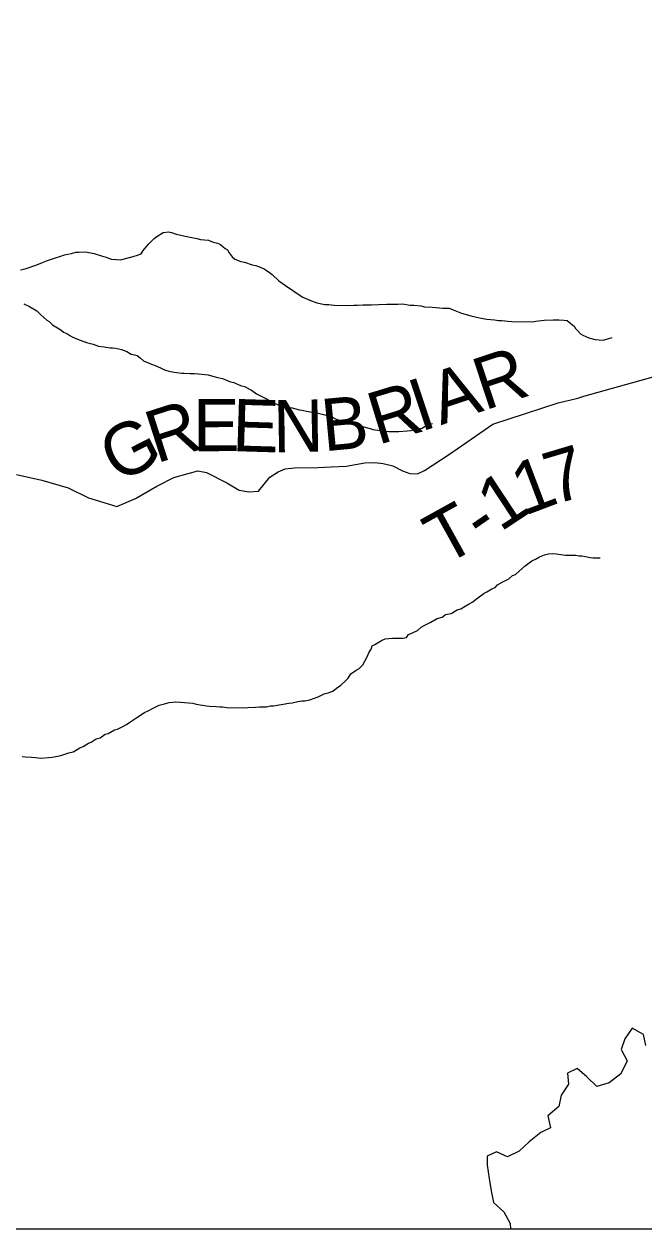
# Model space of a CAD drawing. Extents: x 0 to 34, y 0 to 22.
# Drawn here: x 6.804 to 7.478, y 14.1 to 15.409 of the extents above; entities that cross this region are included whole.
import ezdxf

# ---------------------------------------------------------------- set-up
doc = ezdxf.new("R2010")
doc.units = 0
for name, color, linetype in [('GM_X_Corporation', 7, 'Continuous'), ('GM_X_Major_Lake', 7, 'Continuous'), ('GM_X_Minor_River', 7, 'Continuous'), ('GM_X_Township_Road', 7, 'Continuous'), ('GM_X_Township_Road_Text', 7, 'Continuous'), ('SH_Data', 7, 'Continuous')]:
    doc.layers.add(name, color=color, linetype=linetype)

msp = doc.modelspace()

# ---------------------------------------------------------------- linework, layer by layer
at = {"layer": 'GM_X_Corporation'}
msp.add_lwpolyline([(2.9271, 14.1), (8.843, 14.1), (8.8335, 14.8989), (8.9, 15.0205), (8.9, 18.9286)], dxfattribs=at)
at = {"layer": 'GM_X_Major_Lake'}
msp.add_lwpolyline([(7.4799, 14.2992), (7.4774, 14.3114), (7.465, 14.3181), (7.4572, 14.3064), (7.4532, 14.2951), (7.4595, 14.2828), (7.4528, 14.2685), (7.4401, 14.2588), (7.4267, 14.2548), (7.4159, 14.2653), (7.4054, 14.2742), (7.3947, 14.2694), (7.396, 14.2572), (7.3878, 14.2452), (7.3853, 14.2331), (7.3734, 14.223), (7.3762, 14.21), (7.3659, 14.2049), (7.3532, 14.1948), (7.3424, 14.1844), (7.3294, 14.1785), (7.3177, 14.1836), (7.3073, 14.1789), (7.3076, 14.1694), (7.3096, 14.1549), (7.3117, 14.1412), (7.3145, 14.1286), (7.3257, 14.1185), (7.3324, 14.1058), (7.3328, 14.1)], dxfattribs=at)
at = {"layer": 'GM_X_Minor_River'}
for points in [[(6.8178, 15.1476), (6.8239, 15.1501), (6.8293, 15.1523), (6.8327, 15.1534), (6.8392, 15.1556), (6.8419, 15.1563), (6.848, 15.1585), (6.8514, 15.1592), (6.8556, 15.1598), (6.8602, 15.1613), (6.8636, 15.1616), (6.8709, 15.1619), (6.8803, 15.1598), (6.8894, 15.157), (6.8921, 15.1562), (6.8958, 15.155), (6.8992, 15.1538), (6.9046, 15.1533), (6.9087, 15.1532), (6.9187, 15.1557), (6.9225, 15.1568), (6.9274, 15.1582), (6.9313, 15.1597), (6.9336, 15.1634), (6.9398, 15.1705), (6.9456, 15.1761), (6.9483, 15.1784), (6.9552, 15.1828), (6.9613, 15.1835), (6.9644, 15.1827), (6.9693, 15.1811), (6.981, 15.1786), (6.992, 15.1761), (6.9958, 15.1753), (7.0045, 15.1744), (7.0094, 15.1724), (7.0143, 15.1711), (7.0177, 15.1696), (7.0226, 15.1653), (7.0253, 15.1641), (7.0271, 15.1606), (7.0304, 15.1564), (7.0331, 15.1537), (7.0395, 15.1513), (7.0437, 15.1505), (7.052, 15.1477), (7.0561, 15.1468), (7.0626, 15.1444), (7.0652, 15.1433), (7.0708, 15.1394), (7.0738, 15.137), (7.0809, 15.1301), (7.0847, 15.1277), (7.0918, 15.1226), (7.0949, 15.1207), (7.0997, 15.1172), (7.1069, 15.1125), (7.1095, 15.1113), (7.1148, 15.1093), (7.1224, 15.1065), (7.1311, 15.1045), (7.1353, 15.1044), (7.1413, 15.1039), (7.1562, 15.1036), (7.1626, 15.1039), (7.1664, 15.1038), (7.1725, 15.1041), (7.1813, 15.1043), (7.1893, 15.1046), (7.198, 15.1048), (7.2105, 15.105), (7.2155, 15.1053), (7.2238, 15.104), (7.2276, 15.1039), (7.2352, 15.103), (7.2394, 15.1022), (7.2478, 15.1017), (7.2519, 15.1012), (7.2591, 15.1007), (7.266, 15.1006), (7.2705, 15.0986), (7.2758, 15.0966), (7.2796, 15.095), (7.2834, 15.0942), (7.2898, 15.0922), (7.2943, 15.091), (7.3008, 15.0897), (7.3072, 15.0888), (7.3156, 15.0879), (7.3197, 15.0871), (7.3235, 15.087), (7.33, 15.0865), (7.3342, 15.0861), (7.3566, 15.0857), (7.3604, 15.0864), (7.3695, 15.0874), (7.3791, 15.088), (7.3859, 15.0878), (7.3908, 15.0874), (7.3946, 15.0873), (7.3984, 15.0838)], [(6.8002, 15.1422), (6.8052, 15.1432), (6.8178, 15.1476)], [(6.8038, 15.1052), (6.8098, 15.1025), (6.8177, 15.0978), (6.8222, 15.0935), (6.8286, 15.0877), (6.8312, 15.0861), (6.8349, 15.0826), (6.844, 15.0772), (6.847, 15.0744), (6.8504, 15.0729), (6.8537, 15.0709), (6.8564, 15.0693), (6.862, 15.0669), (6.8651, 15.0658), (6.8719, 15.0634), (6.8791, 15.0613), (6.8851, 15.0593), (6.8912, 15.0585), (6.8976, 15.0576), (6.9003, 15.0575), (6.9033, 15.0571), (6.9101, 15.0558), (6.9158, 15.0535), (6.9203, 15.0507), (6.9241, 15.0499), (6.9271, 15.0491), (6.9301, 15.0467), (6.9339, 15.0433), (6.9426, 15.0397), (6.9467, 15.0381), (6.9524, 15.0357), (6.9565, 15.0337), (6.9614, 15.0321), (6.9671, 15.0309), (6.9755, 15.03), (6.9781, 15.0299), (6.9846, 15.0294), (6.9892, 15.0297), (6.9937, 15.0293), (7.0043, 15.0283), (7.0127, 15.0255), (7.0199, 15.0243), (7.0285, 15.0207), (7.032, 15.0199), (7.0376, 15.0171), (7.0403, 15.0163), (7.0437, 15.0155), (7.0512, 15.0116), (7.0568, 15.0076), (7.0617, 15.0049), (7.0689, 15.0014), (7.0734, 14.9979), (7.0776, 14.9966), (7.0844, 14.9942), (7.0885, 14.993), (7.0954, 14.9921), (7.1033, 14.9901), (7.106, 14.9897), (7.1128, 14.9884), (7.1154, 14.988), (7.12, 14.9872), (7.1238, 14.9863), (7.131, 14.9847), (7.1374, 14.9827), (7.1434, 14.9799), (7.1506, 14.9775), (7.1533, 14.9763), (7.1586, 14.9751), (7.165, 14.9734), (7.1703, 14.9722), (7.1801, 14.9697), (7.1832, 14.9686), (7.1911, 14.9677), (7.1949, 14.9672), (7.2002, 14.9667), (7.2113, 14.9665), (7.2204, 14.9671), (7.2246, 14.9675), (7.2307, 14.9692), (7.2368, 14.9703), (7.2426, 14.974), (7.2452, 14.9747), (7.2479, 14.9754)], [(7.3984, 15.0838), (7.4021, 15.0811), (7.4036, 15.0784), (7.4062, 15.0761), (7.4088, 15.0726), (7.4115, 15.0714), (7.4179, 15.0683), (7.4247, 15.0666), (7.4334, 15.0657), (7.4434, 15.0686)], [(7.2358, 14.7539), (7.2389, 14.7558), (7.2462, 14.7594), (7.2531, 14.7635), (7.2584, 14.7649), (7.2623, 14.7675), (7.2684, 14.7689), (7.2749, 14.7726), (7.2787, 14.7737), (7.2837, 14.7767), (7.288, 14.7792), (7.2918, 14.7815), (7.296, 14.7848), (7.3041, 14.7907), (7.3072, 14.7922), (7.3126, 14.7955), (7.316, 14.797), (7.3187, 14.8), (7.3245, 14.8033), (7.331, 14.8066), (7.3349, 14.81), (7.3383, 14.8111), (7.3425, 14.8152), (7.3487, 14.8204), (7.356, 14.826), (7.3599, 14.8278), (7.3645, 14.8304), (7.3698, 14.8326), (7.374, 14.8336), (7.3786, 14.8339), (7.3824, 14.8335), (7.3926, 14.8322), (7.3964, 14.8321), (7.404, 14.832), (7.4071, 14.8315), (7.4105, 14.8315), (7.4143, 14.8307), (7.4196, 14.8298), (7.4226, 14.8294), (7.4302, 14.8292)], [(6.8019, 14.6135), (6.8054, 14.6131), (6.8122, 14.6126), (6.8164, 14.6122), (6.8224, 14.6117), (6.8304, 14.6123), (6.8346, 14.6126), (6.8384, 14.6133), (6.8438, 14.6143), (6.8526, 14.6172), (6.8575, 14.6183), (6.8618, 14.6209), (6.8648, 14.6227), (6.8683, 14.6242), (6.874, 14.6279), (6.8771, 14.629), (6.8825, 14.6327), (6.8867, 14.6337), (6.8921, 14.6375), (6.8955, 14.6385), (6.9024, 14.6422), (6.9055, 14.6429), (6.9108, 14.6455), (6.9154, 14.6481), (6.9201, 14.6514), (6.9266, 14.6559), (6.9351, 14.661), (6.9397, 14.6632), (6.9435, 14.6655), (6.9466, 14.6669), (6.9508, 14.6691), (6.9565, 14.6706), (6.9619, 14.672), (6.9657, 14.6723), (6.9691, 14.6726), (6.974, 14.6725), (6.9828, 14.6716), (6.9873, 14.6712), (6.9911, 14.6703), (7.0025, 14.6686), (7.0055, 14.6682), (7.0127, 14.6677), (7.0169, 14.6672), (7.0199, 14.6672), (7.0245, 14.6667), (7.0283, 14.6663), (7.0332, 14.6666), (7.0427, 14.6664), (7.0473, 14.6667), (7.0557, 14.6669), (7.0599, 14.6672), (7.0629, 14.6672), (7.0675, 14.6675), (7.072, 14.6685), (7.0751, 14.6685), (7.0812, 14.6695), (7.0858, 14.6702), (7.0919, 14.6712), (7.0953, 14.6716), (7.1018, 14.673), (7.106, 14.6737), (7.1094, 14.674), (7.1147, 14.675), (7.1239, 14.6783), (7.1304, 14.6816), (7.1346, 14.6827), (7.1396, 14.6845), (7.1435, 14.6878), (7.1485, 14.6908), (7.1535, 14.6956), (7.1562, 14.6986), (7.1593, 14.7031), (7.1651, 14.7072), (7.1681, 14.7087), (7.1724, 14.7128), (7.1767, 14.7211), (7.1791, 14.7268), (7.1814, 14.7301), (7.1823, 14.7335), (7.1853, 14.735), (7.1926, 14.7395), (7.1964, 14.7413), (7.2003, 14.7416), (7.2044, 14.7419), (7.2113, 14.7418), (7.2162, 14.7421), (7.2197, 14.7428), (7.222, 14.7458), (7.2262, 14.7476), (7.2316, 14.7502), (7.2358, 14.7539)]]:
    msp.add_lwpolyline(points, dxfattribs=at)
at = {"layer": 'GM_X_Township_Road'}
for points in [[(7.4124, 15.0048), (7.5436, 15.0417), (7.5533, 15.0445), (7.5615, 15.05), (7.7278, 15.156), (7.7386, 15.1623), (7.7463, 15.1686), (7.7654, 15.1857), (8.1779, 15.57), (8.2055, 15.5951), (8.2191, 15.6084), (8.2391, 15.6325), (8.2489, 15.6435), (8.2583, 15.655), (8.2679, 15.6699), (8.2752, 15.6869)], [(6.7957, 14.9198), (6.8233, 14.9136), (6.8519, 14.9053), (6.8742, 14.8945), (6.8906, 14.8893), (6.9048, 14.8849), (6.9253, 14.8938), (6.9485, 14.907), (6.967, 14.9164), (6.9825, 14.921), (6.993, 14.9239), (7.0024, 14.922), (7.0243, 14.9106), (7.038, 14.9029), (7.0484, 14.9008), (7.0589, 14.9018), (7.0713, 14.9169), (7.0803, 14.9228), (7.088, 14.9259), (7.0979, 14.9271), (7.1233, 14.9276), (7.1378, 14.9282), (7.1541, 14.9288), (7.1746, 14.9325), (7.1855, 14.9328), (7.1943, 14.9319), (7.2049, 14.9291), (7.2154, 14.9237), (7.2234, 14.9208), (7.2319, 14.9205), (7.2394, 14.9243), (7.2653, 14.9413), (7.3138, 14.9744), (7.3845, 14.9978), (7.4059, 15.0029), (7.4124, 15.0048)]]:
    msp.add_lwpolyline(points, dxfattribs=at)
at = {"layer": 'SH_Data'}
msp.add_line((2.1, 14.1), (8.9, 14.1), dxfattribs=at)

# ---------------------------------------------------------------- texts
at = {"layer": 'GM_X_Township_Road_Text'}
for s, rotation, p in [('R', 18.3634, (7.3044, 14.9892)), ('A', 18.5657, (7.2571, 14.9733)), ('R', 16.994, (7.1887, 14.9517)), ('I', 18.4655, (7.2348, 14.9659)), ('B', 5.3907, (7.1299, 14.9449)), ('R', 17.8055, (6.9478, 14.9316)), ('E', 0.15, (6.9877, 14.9451)), ('E', 358.2341, (7.0297, 14.9453)), ('N', 0.8092, (7.075, 14.9439)), ('G', 27.1858, (6.9056, 14.9097)), ('7', 16.6145, (7.3795, 14.8866)), ('1', 20.7558, (7.3478, 14.8746)), ('1', 33.4404, (7.3216, 14.8568)), ('T', 28.9289, (7.2603, 14.82)), ('-', 34.4641, (7.3026, 14.8437))]:
    msp.add_text(s, height=0.0568, rotation=rotation, dxfattribs=at).set_placement(p)

doc.saveas('drawing.dxf')
